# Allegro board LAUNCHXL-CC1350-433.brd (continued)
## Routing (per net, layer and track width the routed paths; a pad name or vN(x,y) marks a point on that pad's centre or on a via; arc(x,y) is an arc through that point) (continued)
VDDC: length 16.2
  TOP w0.203: U5.87 8.92,96.22 8.89,96.19 7.29,94.62 U5.115 2.49,94.62 C43.1 C44.1 C45.1
VDDR: length 25.7
  TOP w0.203: v1(27.03,36.55) 27.31,36.83 C16.1
  TOP w0.254: v3(27.58,34.01) 27.58,34.04 27.61,34.06 C9.1 28.42,35.46 28.42,35.61 28.55,35.74 U1.48 ; C16.1 27.38,37.24 U1.45
  TOP w0.508: v3(31.72,46.91) 31.6,46.79 31.12,46.79 ; C8.1 31.12,47.42 31.12,46.79 ; L1.2 31.12,46.79
  L3 w0.508: v3(31.72,46.91) 31.12,46.91 30.99,46.79 28.32,46.79 27.81,46.28 26.87,46.28 26.37,45.77 26.37,36.5 ; v1(27.03,36.55) 26.42,36.55 26.37,36.5 ; 26.37,36.5 26.37,35.89 27.58,34.67 v3(27.58,34.01)
VDDS: length 46.3
  TOP w0.203: v1(23.7,31.19) R67.1
  TOP w0.254: v3(37.47,41) 37.01,40.54 C4.1 36.83,40.23 U1.22 ; C7.1 29.87,43.61 30.58,42.9 U1.34 ; U1.44 27.94,37.72 v1(27.89,37.77) 27.36,37.77 C5.1 ; U1.13 36.78,35.74 C3.1 36.91,35.59 36.68,35.36 v3(36.68,35.05)
  TOP w0.406: 27.31,44.65 R1.2 27.38,43.71 C6.1 29.59,43.71 C7.1
  TOP w0.508: FL1.1 27.69,44.27 v3(27.84,44.27)
  L3 w0.203: v1(23.7,31.19) 26.06,31.19 28.32,33.45 28.32,37.34
  L3 w0.305: 28.32,37.34 v1(27.89,37.77)
  L3 w0.508: 27.89,42.85 27.89,43.61 27.84,43.66 v3(27.84,44.27) ; 27.89,42.85 27.94,42.9 35.56,42.9 36.68,41.78 36.68,40.97 ; 27.89,42.85 v1(27.89,37.77) ; v3(37.47,41) 36.7,41 36.68,40.97 ; 36.68,40.97 v3(36.68,35.05)
CC1350_RESET: length 77
  TOP w0.152: CR8.2 38.71,74.07 38.56,73.91 v1(38.56,73.71) ; R52.1 R51.2 ; v1(38.61,72.16) 38.91,71.86 45.95,71.86 46.41,72.31 46.41,75.34 45.67,76.05 P5.10
  TOP w0.203: R1.1 27.81,42.72 27.97,42.88 29.85,42.88 30.1,42.62 U1.35 ; C20.1 v1(24.82,42.72) ; 43.13,70 43.13,71.68 42.95,71.86 ; v1(38.61,72.16) 38.15,72.16 36.73,73.58 v1(25.48,73.58) v1(25.48,69.29)
  TOP w0.305: R1.1 C20.1
  L3 w0.152: v1(38.56,73.71) 38.56,73.23 38.61,73.18 v1(38.61,72.16)
  L3 w0.203: v1(25.48,73.58) 25.48,74.4 24.16,75.72 P4.12 ; v1(25.48,69.29) 25.48,52.96 24.82,52.3 v1(24.82,42.72)
CC1350_RXD: length 93.5
  TOP w0.203: v1(42.42,33.45) 41.38,32.41 34.11,32.41 32.59,33.93 U1.7 ; v1(42.42,59.21) 42.09,59.54 v1(19.08,59.54) 7.67,59.54 J1.7 ; v1(19.08,69.37) v1(19.08,73.46)
  L3 w0.203: v1(42.42,33.45) v1(42.42,59.21) ; v1(19.08,69.37) v1(19.08,59.54) ; P4.16 v1(19.08,73.46)
CC1350_SW_PWR: length 46.3
  TOP w0.203: v1(16.42,50.69) 16.41,50.67 J1.16 ; v1(24.59,32.11) R69.2 ; U1.43 27.81,38.23 27.38,38.66 v1(16.94,38.66)
  L3 w0.203: v1(16.42,50.69) 16.94,50.16 v1(16.94,38.66) 16.94,33.1 17.93,32.11 v1(24.59,32.11)
CC1350_SWO: length 52.7
  TOP w0.203: v1(34.77,44.91) 34.77,43.87 33.58,42.67 U1.28 ; v1(35.28,69.62) v1(35.28,72.16) ; J2.9 v1(35.15,58.29)
  L3 w0.203: v1(35.28,69.62) 35.28,65.13 35.64,64.77 35.64,58.78 v1(35.15,58.29) 34.77,57.91 v1(34.77,44.91) ; v1(35.28,72.16) 35.28,76.56 36.35,77.62 36.35,77.65 36.86,78.16 P4.2
CC1350_TCK: length 67.4
  TOP w0.152: 38.71,76.68 38.96,76.94 39.45,76.94 39.57,76.81 41.33,76.81 41.86,77.34 P5.4 ; 38.71,76.68 CR8.6 ; 38.71,76.68 v1(38.71,77.5)
  TOP w0.203: v1(37.26,77.04) 29.39,77.04 29.24,77.19 29.24,78.61 ; U1.25 35.08,42.37 v1(36.7,43.99) ; v1(36.7,50.7) R47.2 ; v1(37.57,68.58) 29.54,68.58 29.24,68.88 v1(29.24,72.95)
  L3 w0.203: v1(37.57,68.58) 37.57,56.46 37.08,55.98 37.08,52.2 36.7,51.82 v1(36.7,50.7) v1(36.7,43.99) ; v1(37.26,77.04) 38.25,77.04 v1(38.71,77.5) ; v1(29.24,72.95) 29.24,78.61
CC1350_TMS: length 67.9
  TOP w0.152: P5.2 38.51,78.1 38.2,77.8 CR8.7
  TOP w0.203: CR8.7 36.63,76.3 35.31,74.98 v1(28.58,74.98) v1(26.7,74.98) ; v1(28.58,72.67) 28.58,68.63 29.51,67.69 v1(38.28,67.69) ; U1.24 35.81,42.44 36.53,43.15 36.98,43.15 v1(37.64,43.81) ; R46.2 v1(37.64,53.21)
  L3 w0.203: v1(37.64,43.81) v1(37.64,53.21) 37.64,54.97 38.28,55.6 v1(38.28,67.69) ; P4.10 v1(26.7,74.98) ; v1(28.58,72.67) v1(28.58,74.98)
CC1350_TXD: length 90.9
  TOP w0.203: U1.8 33.1,33.93 34.14,32.89 40.92,32.89 v1(41.76,33.73) ; v1(40.16,62.08) v1(20.35,62.08) 7.67,62.08 J1.5 ; v1(21.62,69.49) v1(21.62,73.56)
  L3 w0.203: v1(21.62,69.49) 21.62,67.08 20.35,65.81 v1(20.35,62.08) ; v1(41.76,33.73) 41.76,43.69 40.77,44.68 40.77,61.47 v1(40.16,62.08) ; v1(21.62,73.56) 21.62,78.61
CC1350_VDD: length 157.6
  TOP w0.254: R59.2 47.57,31.88 47.12,32.33 R11.2 v3(46.3,32.46)
  TOP w0.305: v1(27.1,47.75) R2.2 R3.2 ; U4.8 C30.1 ; CR8.8 37.69,75.56 37.21,75.06 v1(37.21,74.8) 37.21,74.29 38.56,72.95 39.5,72.95 40.06,73.51 P5.1
  TOP w0.508: v3(11.73,71.3) 7.34,71.3 6.38,70.33 J1.1 ; R60.2 47.12,36.09 C30.1 47.09,35.41 v3(46.3,35.41) ; FL1.2 v1(27.1,47.75)
  L3 w0.254: v3(46.3,35.41) v3(46.3,32.46)
  L3 w0.305: 39.5,71.3 39.7,71.5 39.7,74.22 39.12,74.8 v1(37.21,74.8)
  L3 w0.508: P4.18 16.54,71.3 ; 16.54,71.3 v3(11.73,71.3) ; 16.54,71.3 27.1,71.3 ; v1(27.1,47.75) 27.1,71.3 ; 27.1,71.3 49.91,71.3 ; 49.91,71.3 54,71.3 55.7,69.6 55.7,45.87 54.84,45.01 54.84,36.14 54.31,35.61 52.27,35.61 P1.1 46.99,35.43 46.96,35.41 v3(46.3,35.41) ; 49.91,71.3 P10.3
DCDC_SW: length 2.4
  TOP w0.305: U1.33 31.09,44.37 L1.1
DIO1_RF_SW: length 85.8
  TOP w0.203: v1(43.05,33.1) 41.91,31.95 v1(34.29,31.95) 34.26,31.98 34.01,31.98 32.08,33.91 U1.6 ; J1.20 v1(10.67,45.59) ; v1(11.94,56.31) 24.13,56.31 25.98,54.46 v1(43.05,54.46) ; v1(31.06,29.44) U11.6
  L3 w0.203: v1(43.05,33.1) v1(43.05,54.46) ; v1(10.67,45.59) 11.15,46.08 11.15,55.52 v1(11.94,56.31) ; v1(31.06,29.44) 31.39,29.11 33.43,29.11 33.96,29.64 33.96,31.62 v1(34.29,31.95)
DIO4_SCL: length 78
  TOP w0.203: J1.17 7.72,46.79 v1(11.96,46.79) 22.05,46.79 23.01,47.75 R2.1 ; v1(41.12,33.99) 40.49,33.35 34.29,33.35 33.58,34.06 U1.9 ; v1(12.5,51.33) v1(40.08,51.33)
  L3 w0.203: v1(41.12,33.99) 41.12,43.1 40.08,44.15 v1(40.08,51.33) ; v1(12.5,51.33) 11.96,50.8 v1(11.96,46.79)
DIO5_SDA: length 71.8
  TOP w0.203: U1.10 34.09,34.16 34.49,33.76 40.03,33.76 v1(40.44,34.16) ; R3.1 24.18,46.71 23.67,46.71 20.9,43.94 v1(18.01,43.94) 8.03,43.94 J1.19 ; v1(39.47,49.63) 36.42,49.63 35.36,50.7 v1(18.01,50.7)
  L3 w0.203: v1(39.47,49.63) 39.47,43.76 40.44,42.8 v1(40.44,34.16) ; v1(18.01,50.7) v1(18.01,43.94)
DIO6_RLED: length 82.6
  TOP w0.203: J2.3 v1(40.26,65.91) ; U1.11 34.59,34.32 34.77,34.14 39.47,34.14 v1(39.8,34.47) ; v1(38.94,48.92) 36.22,48.92 35.03,50.11 v1(13.61,50.11)
  L3 w0.203: v1(39.8,34.47) 39.8,42.52 38.94,43.38 v1(38.94,48.92) 38.94,53.95 39.45,54.46 39.45,65.1 v1(40.26,65.91) ; v1(13.61,50.11) 12.67,49.17 12.67,41.63 P6.2
DIO7_GLED: length 97.8
  TOP w0.203: v1(39.24,34.77) 39.01,34.54 35.2,34.54 35.08,34.67 U1.12 ; J2.1 47.45,68.45 45.82,66.83 v1(38.94,66.83) v1(15.11,66.83)
  L3 w0.203: v1(38.94,66.83) 38.94,55.27 38.3,54.64 38.3,42.8 39.24,41.86 v1(39.24,34.77) ; P6.4 v1(15.11,66.83)
DIO8_MISO: length 45.1
  TOP w0.203: v1(46.81,51.92) 50.83,51.92 J2.14 ; U4.2 v1(48.67,32.46) ; U1.14 v1(44.48,36.22) ; v1(50.29,36.32) 50.32,36.35 ; 50.32,36.35 50.32,37.31 49.91,37.72 v1(47.98,37.72) ; 50.32,36.35 v1(50.32,34.37)
  L3 w0.203: v1(48.67,32.46) 50.11,32.46 50.32,32.66 v1(50.32,34.37) ; v1(47.98,37.72) 47.98,40.46 46.33,42.11 46.33,51.44 v1(46.81,51.92) ; v1(44.48,36.22) 46.1,36.22 46.33,35.99 49.96,35.99 v1(50.29,36.32)
DIO9_MOSI: length 40.3
  TOP w0.203: v1(46.48,54.46) 50.83,54.46 J2.12 ; 35.81,36.73 46.61,36.73 v1(46.99,37.11) 47.02,37.13 49.56,37.13 49.66,37.03 U4.5
  L3 w0.203: v1(46.99,37.11) 47.04,37.11 47.47,37.54 47.47,40.34 45.92,41.88 45.92,53.9 v1(46.48,54.46)
DIO10_SCLK: length 69
  TOP w0.203: J1.13 7.62,51.97 44.35,51.97 v1(44.68,51.64) ; U1.16 v1(46.25,37.24) ; v1(49.15,36.5) U4.6
  L3 w0.203: v1(44.68,51.64) 44.68,41.43 46.25,39.85 v1(46.25,37.24) 46.25,36.78 46.53,36.5 v1(49.15,36.5)
DIO11_CS: length 43.6
  TOP w0.203: v1(45.29,62.13) 50.88,62.13 J2.6 ; U1.17 v1(46.96,37.72)
  L3 w0.203: v1(46.96,37.72) 46.96,39.9 45.29,41.58 v1(45.29,62.13)
DIO12: length 46.2
  TOP w0.203: v1(46.58,64.36) 46.91,64.69 50.9,64.69 J2.4 ; U1.18 v1(48.44,38.23)
  L3 w0.203: v1(48.44,38.23) 48.44,40.64 46.71,42.37 46.71,50.67 47.27,51.23 47.27,57.58 46.58,58.27 v1(46.58,64.36)
DIO13_BTN1: length 97.5
  TOP w0.203: v1(47.29,65.28) 40.82,65.28 40.08,64.54 28.17,64.54 27.25,65.46 v1(17.73,65.46) ; J2.16 50.88,49.43 47.5,49.43 v1(47.17,49.1) ; v1(17.73,69.04) 17.73,73.51 17.04,74.19 7.52,74.19 R56.2 ; v1(49.02,38.73) U1.19
  L3 w0.203: v1(49.02,38.73) 48.79,38.96 48.79,40.84 47.17,42.47 v1(47.17,49.1) 47.17,50.19 47.78,50.8 47.78,64.8 v1(47.29,65.28) ; v1(17.73,65.46) v1(17.73,69.04)
DIO14_BTN2: length 56.3
  TOP w0.203: R55.2 48.51,70.89 v1(47.98,70.36) ; U1.20 v1(49.35,39.22) ; v1(47.83,46.86) 50.85,46.86 J2.18
  L3 w0.203: v1(49.35,39.22) 49.35,41.2 47.83,42.72 v1(47.83,46.86) 48.16,47.19 48.16,69.72 47.98,69.9 v1(47.98,70.36)
DIO15: length 21.7
  TOP w0.203: U1.21 v1(49.91,39.73)
  L3 w0.203: v1(49.91,39.73) 49.91,43.97 50.44,44.5 51.77,44.5 51.97,44.7 51.97,45.44 J2.20
DIO16_TDO: length 61.6
  TOP w0.152: P5.6 43.13,77.34 42.09,76.3 v1(39.8,76.3) CR8.5
  TOP w0.203: U1.26 34.59,42.62 35.99,44.02 v1(35.99,44.17) ; v1(35.99,48.08) 36.14,48.08 36.17,48.11 R48.2 ; v1(35.92,76.3) v1(31.8,76.3) ; v1(36.93,69.82) 36.93,72.36 36.5,72.8 v1(31.8,72.8)
  L3 w0.203: v1(35.99,44.17) v1(35.99,48.08) 35.99,56.24 36.96,57.2 36.96,67.67 36.5,68.12 36.5,69.39 v1(36.93,69.82) ; 31.78,78.61 31.78,76.33 v1(31.8,76.3) v1(31.8,72.8) ; v1(35.92,76.3) v1(39.8,76.3)
DIO17_TDI: length 57.6
  TOP w0.152: P5.8 44.4,77.34 42.95,75.9 41.28,75.9 v1(39.19,73.81) CR8.3
  TOP w0.203: v1(35.99,70.21) v1(35.99,72.26) ; v1(36.63,74.32) v1(34.32,74.32) ; U1.27 34.09,42.62 35.33,43.87 35.33,45.49 v1(35.43,45.59) R49.2
  L3 w0.152: 38.68,74.32 v1(39.19,73.81)
  L3 w0.203: v1(35.99,72.26) 35.99,73.69 v1(36.63,74.32) 38.68,74.32 ; v1(35.99,70.21) 35.99,65.3 36.3,65 36.3,57.91 35.43,57.05 v1(35.43,45.59) ; v1(34.32,74.32) P4.4
DIO19_CTS: length 34.4
  TOP w0.203: J2.7 35.36,60.83 35.33,60.86 v1(34.87,60.86) ; U1.29 33.1,42.77 34.32,43.99 v1(34.32,45.52)
  L3 w0.203: v1(34.32,45.52) 34.32,60.3 v1(34.87,60.86)
DIO20_FLASH_CS: length 65.9
  TOP w0.203: v1(43.76,33.38) R11.1 ; U1.30 32.59,42.93 33.68,44.02 v1(33.68,46.33) 40.16,46.33 40.72,46.89 v1(43.76,46.89) ; J2.5 v1(34.06,63.37)
  TOP w0.254: U4.1 47.96,33.05 47.62,33.38 R11.1
  L3 w0.203: v1(43.76,46.89) v1(43.76,33.38) ; v1(34.06,63.37) 33.68,62.99 v1(33.68,46.33)
DIO21: length 35
  TOP w0.203: J1.15 7.62,49.43 v1(32.99,49.43) ; U1.31 32.08,43.03 32.99,43.94 v1(32.99,45.24)
  L3 w0.203: v1(32.99,49.43) v1(32.99,45.24)
DIO22: length 41.5
  TOP w0.203: v1(31.75,57.02) 7.65,57.02 J1.9 ; v1(32.33,44.53) 32.33,43.97 31.6,43.23 U1.32
  L3 w0.203: v1(32.33,44.53) 32.33,56.44 v1(31.75,57.02)
DIO23_ANALOG: length 47.6
  TOP w0.203: v1(24.05,64.49) 23.75,64.8 9.88,64.8 9.75,64.67 7.62,64.67 J1.3 ; U1.36 29.59,42.37 29.44,42.52 28.37,42.52 27.76,41.91 24.36,41.91 v1(24.16,42.11)
  L3 w0.203: v1(24.16,42.11) 24.16,53.11 24.87,53.82 24.87,63.68 v1(24.05,64.49)
DIO24_ANALOG: length 35.7
  TOP w0.203: U1.37 28.32,41.22 28.12,41.43 23.72,41.43 v1(23.42,41.73) ; J1.11 7.67,54.46 22.99,54.46 v1(23.42,54.03)
  L3 w0.203: v1(23.42,41.73) v1(23.42,54.03)
DIO25_ANALOG: length 42.1
  TOP w0.203: v1(22.02,63.58) 10.62,63.58 10.41,63.37 J1.6 ; U1.38 28.22,40.72 27.91,41.02 23.06,41.02 v1(22.61,41.48)
  L3 w0.203: v1(22.02,63.58) 22.33,63.27 22.35,63.27 22.61,63.02 v1(22.61,41.48)
DIO26_ANALOG: length 39.5
  TOP w0.203: v1(20.9,60.76) 8.99,60.76 J1.8 ; U1.39 28.09,40.23 27.74,40.59 22.25,40.59 v1(21.67,41.17)
  L3 w0.203: v1(21.67,41.17) 21.67,59.99 v1(20.9,60.76)
DIO27_ANALOG: length 37.6
  TOP w0.203: U1.40 28.02,39.73 27.66,40.08 21.06,40.08 v1(20.6,40.54) ; v1(20.17,57.94) 19.81,58.29 J1.10
  L3 w0.203: v1(20.6,40.54) 20.6,57.51 v1(20.17,57.94)
DIO28_ANALOG: length 35.4
  TOP w0.203: v1(18.97,55.45) 10.29,55.45 9.98,55.75 J1.12 ; v1(19.69,39.95) 20.07,39.57 27.56,39.57 27.91,39.22 U1.41
  L3 w0.203: v1(19.69,39.95) 19.69,40 19.58,40.11 19.58,54.84 v1(18.97,55.45)
DIO29_ANALOG: length 34.3
  TOP w0.203: U1.42 27.84,38.73 27.46,39.12 18.8,39.12 v1(18.39,39.52) ; v1(18.19,53.24) 10.01,53.24 9.98,53.21 J1.14
  L3 w0.203: v1(18.39,39.52) 18.87,40 18.87,52.55 v1(18.19,53.24)
IRSTN: length 17.3
  TOP w0.152: v1(6.83,109.5) 7.34,110.01 9.96,110.01 11.07,108.89 11.07,105.64 11.81,104.9 R20.2 ; v1(3.51,106.1) 5.31,107.9 v1(5.31,109.5)
  L3 w0.152: v1(5.31,109.5) v1(6.83,109.5)
ITCK: length 12.4
  TOP w0.152: v1(2.11,110.01) 0.81,108.71 0.81,101.5 1.7,100.61 U5.100
ITDI: length 10.3
  TOP w0.152: U5.98 1.8,101.4 1.45,101.75 1.45,105.18 2.79,106.53 2.79,108.13 v1(3.38,108.71)
ITDO: length 13.2
  TOP w0.152: U5.97 2.08,101.8 1.8,102.08 1.8,105.11 4.8,108.1 4.8,109.91 v1(3.4,111.3)
ITMS: length 9.2
  TOP w0.152: U5.99 2.84,101.02 2.82,100.99 1.75,100.99 1.14,101.6 1.14,106.55 v1(2.11,107.49)
LP_RESET: length 17.4
  TOP w0.203: J2.10 50.9,59.51 v1(46,59.51) ; v1(45.67,68.4) R51.1
  L3 w0.203: v1(45.67,68.4) 46,68.07 v1(46,59.51)
Net_7: length 1.7
  TOP w0.152: 19.2,92.61 20.29,92.61 v1(20.7,93.01)
Net_24:
  vias: v2(21.59,7.19) v2(23.6,2.18)
Net_25:
  vias: v2(19.61,7.19) v2(21.59,2.18)
Net_26:
  vias: v2(17.6,7.19) v2(19.61,2.18)
Net_27:
  vias: v2(15.6,7.19) v2(17.6,2.18)
Net_28:
  vias: v2(13.59,7.19) v2(15.6,2.18)
Net_29:
  vias: v2(11.61,7.19) v2(13.59,2.18)
Net_30:
  vias: v2(9.6,7.19) v2(11.61,2.18)
Net_31:
  vias: v2(7.59,7.19) v2(9.6,2.18)
Net_32:
  vias: v2(5.61,7.19) v2(5.61,2.18) v2(7.59,2.18)
Net_33:
  vias: v2(23.6,7.19) v2(25.6,2.18)
USB_DM: length 14.1
  TOP w0.152: J6.2 10.74,114 v1(10.74,112.88) 10.8,112.83 10.8,112.19 CR6.5 ; v1(8.69,110.9) 7.29,110.9 6.4,110.01 6.4,104.11 6.5,104.01 U5.93
  L3 w0.152: v1(10.74,112.88) 9.07,111.2 v1(8.69,110.9)
USB_DP: length 15.7
  TOP w0.152: CR6.4 11.3,112.8 v1(11.38,112.88) 11.4,112.9 J6.3 ; U5.94 6.1,110.44 7.04,111.38 8.92,111.38 v1(9.42,110.87)
  L3 w0.152: v1(11.38,112.88) v1(9.42,110.87)
USB_ID: length 14.6
  TOP w0.152: CR6.2 10.8,111.61 v1(10.8,111) 10.11,111 9.4,111.71 6.78,111.71 5.79,110.72 5.79,106.88 5.59,106.68 R19.2 ; J6.4 12.04,114 v1(12.04,112.85)
  L3 w0.152: v1(10.8,111) 10.8,111.66 11.68,112.55 11.73,112.55 v1(12.04,112.85)
USB_VBUS: length 56.2
  TOP w0.152: U7.8 v1(14.71,110.59) ; R22.2 v1(3.56,86.51)
  TOP w0.203: R66.1 3.38,103.78 3.07,103.78 v1(2.59,103.3)
  TOP w0.305: U7.2 U7.1 11.71,110.59 12.19,111.07 C48.1 ; J6.1 10.11,112.9 v1(10.08,112.88) 10.08,112.42 CR6.6
  TOP w0.508: v1(12.19,111.91) C48.1
  L3 w0.508: P4.19 11.86,83.31 7.37,83.31 4.17,86.51 v1(3.56,86.51) 0.76,89.31 0.76,103.4 ; 11.23,110.11 4.7,110.11 3.94,109.35 1.85,109.35 0.76,108.25 0.76,103.4 ; v1(2.59,103.3) 0.84,103.3 0.76,103.4
V-SENSE: length 41.6
  TOP w0.152: v1(25.7,85.12) C55.1 U10.2 ; v1(21.69,85.12) C53.1 U8.2 ; v1(29.69,85.12) C57.1 U9.2
  TOP w0.305: 38.66,85.8 38.66,86.74 39.8,87.91 44.91,87.91 45.69,87.1 P7.1 47.19,86.51 47.9,85.8 47.9,83.16 P10.2 ; 38.66,85.8 38.35,85.5 36.2,85.5 34.75,84.05 30.76,84.05 v1(29.69,85.12) ; 38.66,85.8 CR7.8
  L3 w0.305: v1(21.69,85.12) 22.05,84.76 22.83,84.76 22.89,84.71 24.82,84.71 25.22,85.12 v1(25.7,85.12) 26.19,85.12 26.57,84.71 28.83,84.71 29.21,85.12 v1(29.69,85.12)
XDS_RESET: length 11.6
  TOP w0.152: U10.1 23.77,84.71 23.57,84.91 23.57,85.93 23.52,86 U10.6 v1(23.52,87.71) ; v1(22.81,89.71) 21.79,90.7 21.79,91.8 R58.1 20.85,92.3 20.75,92.2 U5.40
  L3 w0.152: v1(22.81,89.71) 23.5,89.71 23.8,89.41 23.8,87.99 v1(23.52,87.71)
XDS_RESET_LS: length 64.6
  TOP w0.152: R57.2 v1(16.99,114.3) ; P7.10 38.79,81.92 36.83,83.87 v1(36.83,83.95) 37.29,84.4 CR7.2 ; v1(23.5,83.41) 23.5,84.07 U10.15 23.52,82.98 24.16,82.35 P4.11
  L3 w0.152: 29.87,84.53 30.3,84.96 30.3,86.11 26.9,89.51 25.3,89.51 25.27,89.48 24.43,89.48 23.75,90.17 23.75,113.33 22.78,114.3 v1(16.99,114.3) ; 29.87,84.53 29.51,84.53 29.29,84.3 24.41,84.3 v1(23.5,83.41) ; 29.87,84.53 30.53,84.53 30.76,84.3 36.47,84.3 v1(36.83,83.95)
XDS_RX: length 3.1
  TOP w0.152: U8.8 18.69,86.89 19.13,87.33 19.13,89.33 U5.33
XDS_RX_LS: length 10.5
  TOP w0.152: R61.2 21.72,81.25 20.32,79.86 18.01,79.86 17.75,80.11 17.75,82.47 18.69,83.41 U8.13
XDS_SWO: length 7.2
  TOP w0.152: U5.25 14.91,88.75 15.06,88.9 17.96,88.9 18.11,88.75 18.11,86.31 U8.9
XDS_SWO_LS: length 23.8
  TOP w0.152: U8.12 v1(17.81,84.71) ; R62.2 v1(36.4,83.26) 36.86,82.8 P4.1
  L3 w0.152: v1(17.81,84.71) 19.81,82.7 26.9,82.7 27.43,83.24 30.28,83.24 30.89,83.85 35.81,83.85 v1(36.4,83.26)
XDS_TCK: length 10.4
  TOP w0.152: v1(23.29,89.2) 23.6,88.9 25.7,88.9 27.51,87.1 U9.6 ; U5.35 19.2,90.2 20.14,90.2 20.7,89.66 v1(20.7,89.2)
  L3 w0.152: v1(23.29,89.2) v1(20.7,89.2)
XDS_TDI: length 10.2
  TOP w0.152: U9.7 27.1,87.05 25.58,88.57 23.22,88.57 20.52,91.26 20.5,91.26 20.35,91.41 U5.38
XDS_TDI_LS: length 26.6
  TOP w0.152: CR7.3 37.9,83.54 38.63,82.8 40.01,82.8 40.41,83.21 41.35,83.21 41.88,82.65 P7.8 41.88,81.15 40.69,79.96 34.9,79.96 ; 34.9,79.96 28.45,79.96 27.94,80.47 27.94,81.86 27.1,82.7 U9.14 ; 34.9,79.96 34.34,80.52 34.34,81.13 P4.3
XDS_TDO: length 10.1
  TOP w0.152: U9.9 26.29,86.11 26.29,87.3 25.4,88.19 23.11,88.19 20.29,91.01 U5.37
XDS_TDO_LS: length 31.6
  TOP w0.152: 43.23,80.31 R63.2 43.23,80.31 ; 43.23,80.31 43.23,79.96 42.82,79.55 v1(41.15,79.55) ; 43.23,80.31 43.15,80.37 P7.6 43.15,82.65 41.91,83.9 39.4,83.9 CR7.5 ; v1(25.45,82.22) 25.45,82.75 25.81,83.11 25.81,84.25 26.26,84.71 U9.12
  L3 w0.152: 31.89,79.93 25.76,79.93 25.45,80.24 v1(25.45,82.22) ; 31.89,79.93 40.34,79.93 ; 31.89,79.93 31.89,81.04 31.78,81.15 ; 40.36,79.93 40.74,79.55 v1(41.15,79.55)
XDS_TMS: length 6.1
  TOP w0.152: U10.8 22.71,88.09 20.19,90.6 U5.36
XDS_TMS_DIR: length 12.9
  TOP w0.152: v1(18.59,87.5) 18.59,88.8 18.19,89.2 14.86,89.2 14.5,88.85 U5.24 ; U10.5 23.9,87.12 v1(24,87.2)
  L3 w0.152: v1(18.59,87.5) 18.9,87.2 v1(24,87.2)
XDS_TMS_LS: length 34.6
  TOP w0.152: U10.13 22.71,82.8 22.89,82.63 22.89,80.42 23.44,79.86 25.4,79.86 P4.9 ; R65.2 46.3,82.02 46.18,81.92 P7.2 45.69,83.9 44.7,84.91 v1(41,84.91) CR7.7
  L3 w0.152: v1(41,84.91) 41,84 39.27,82.27 27.81,82.27 P4.9
XDS_TX: length 4.5
  TOP w0.152: U8.6 19.51,88.52 20.19,89.2 20.19,89.66 20.04,89.81 U5.34
XDS_TX_LS: length 3.4
  TOP w0.152: P4.15 19.81,81.89 19.81,83.26 19.51,83.54 U8.15
XDS_VCC: length 86.7
  TOP w0.152: v1(29.69,85.9) C56.1 U9.4 U9.3 ; C38.1 17.12,105.82 R17.2 17.12,106.63 v1(17.09,106.65) ; R33.2 C47.1 v1(16.61,109.5) ; v1(8.89,85.09) R18.2 8.89,85.7 8.79,85.6 C42.1 ; v1(20.7,91.69) 21.03,91.39 R58.2 ; U8.3 U8.4 C52.1 v1(21.69,85.9) ; v1(25.7,85.9) C54.1 U10.4 U10.3
  TOP w0.203: 15.49,86.51 C35.1 v1(15.49,85.85) ; 15.49,86.51 15.29,86.72 15.29,87.91 U5.26 ; 15.49,86.51 16.1,87.1 U5.28 ; U5.39 19.2,91.8 20.6,91.8 v1(20.7,91.69) ; v1(21.89,103) R39.1 R27.1 ; U5.113 2.39,95.4 C36.1 v1(1.65,95.5) ; U5.52 U5.51 19.2,96.6 C39.1 C40.1 v1(22.3,96.6) ; U5.101 2.59,100.2 C37.1 v1(1.75,100) ; v1(22.61,99.69) R30.2 ; v1(7.59,104.39) 7.7,104.29 U5.90 ; U5.122 3.81,91.8 v1(2.74,91.8) ; U5.69 16.1,104.34 16.21,104.44 C38.1 ; U5.47 v1(20.27,95) ; v1(11.43,86.72) 11.3,86.84 U5.16 ; v1(12.09,104.37) 12.09,103.33 U5.79 ; U5.7 U5.8 8.1,86.69 C41.1 C42.1 ; R31.2 v1(20.6,104.9)
  TOP w0.305: P10.1 49.91,87 48.31,88.6 37.59,88.6 35.89,86.89 30.71,86.89 v1(29.69,85.9) ; U7.3 U7.4 C49.1 v1(11.71,106.3)
  L3 w0.152: v1(16.61,109.5) 16.61,107.11
  L3 w0.305: 17.6,87.5 18.59,86.51 21.11,86.51 v1(21.69,85.9) 22.1,86.31 25.3,86.31 v1(25.7,85.9) 26.04,86.23 29.36,86.23 v1(29.69,85.9) ; P4.17 16.54,84.81 v1(15.49,85.85)
  L3 w0.508: 15.19,85.19 15.24,85.19
  vias: v1(2.01,106.4)
N1013277: length 7.1
  TOP w0.254: Y2.3 22.96,36.25 23.93,35.28 23.93,35.23 25.12,35.23 25.81,35.92 27.33,35.92 28.14,36.73 28.85,36.73
N1013855: length 4.2
  TOP w0.203: 27.95,28.05 27.97,28.04 28.91,28.98 U11.10
  TOP w0.305: 27.95,28.05 27.97,28.04 27.94,28.04 C11.1 L12.1
N1013859: length 3.9
  TOP w0.203: L30.1 29.39,28.19 U11.1
  TOP w0.305: C22.1 27.74,26.39 L27.1 27.84,26.64 L30.1
N1013907: length 3.2
  TOP w0.356: 26.33,24.98 26.34,24.99 25.65,24.99 25.58,25.1 ; 25.58,25.1 25.58,25.68 25.57,25.67 ; 25.58,25.1 C12.1 L13.1
N1013927: length 2.1
  TOP w0.305: 23.71,23.23 C13.1 L14.1
N1013977: length 3.6
  TOP w0.356: A1.1 L33.1 C71.2
N1014101: length 10.5
  TOP w0.203: Y1.1 35.41,28.83 34.7,28.83 34.19,29.34 34.19,30.76 31.75,33.2 31.52,33.2 31.09,33.63 U1.4
  TOP w0.305: C17.1 37.16,28.42 36.3,28.42 36.07,28.65 Y1.1
N1014113: length 8
  TOP w0.203: Y1.2 34.32,31.14 31.6,33.86 U1.5
  TOP w0.305: Y1.2 36.17,31.14 36.4,31.37 C18.1
N1018952: length 5
  TOP w0.254: U1.47 28.42,36.22 27.53,35.33 26.19,35.33 25.5,34.65 25.22,34.65 Y2.1
N1105722: length 1.4
  TOP w0.305: R15.1 CR1.2
N1105771: length 1.3
  TOP w0.305: CR2.2 12.55,34.62 R14.1
N1105824: length 2.2
  TOP w0.305: P6.1 12.57,36.86 R14.2
N1106228: length 2.1
  TOP w0.305: P6.3 R15.2
N1176544: length 6.4
  TOP w0.254: R46.1 J2.13
N1176548: length 6.4
  TOP w0.254: R47.1 48.44,50.7 48.46,50.67 J2.15
N1176568: length 6.4
  TOP w0.203: J2.17 43.23,48.13 R48.1
N1177007: length 6.4
  TOP w0.254: R49.1 J2.19
N1240270: length 23
  TOP w0.152: U9.15 27.51,83.31 27.58,83.24 28.14,83.24 v1(28.68,82.7) 28.73,82.7 28.88,82.55 28.91,82.55 29.24,82.22 29.24,81.15 ; P7.4 44.42,83.13 43.15,84.4 v1(40.21,84.4) CR7.6
  L3 w0.152: v1(28.68,82.7) 37.9,82.7 39.6,84.4 v1(40.21,84.4)
N1288065: length 1.8
  TOP w0.152: SW2.3 54.71,72.77 54.71,72.14 54.38,71.81 R55.1
N1288098: length 1.3
  TOP w0.152: R56.1 5.08,72.72 SW1.4
N1299607: length 22.1
  TOP w0.203: J2.11 v1(41.58,55.75) ; v1(41.2,68.5) 41.81,68.5 41.83,68.53 42.16,68.53 R52.2
  L3 w0.203: v1(41.2,68.5) 41.2,56.13 v1(41.58,55.75)
N1384129: length 4.7
  TOP w0.152: R57.1 19.71,115.6 SW3.3
N1393569: length 1.6
  TOP w0.254: C19.1 36.65,41.25 36.65,40.97 36.4,40.72 U1.23
N1403554: length 9.4
  TOP w0.203: U1.3 30.58,33.6 30.96,33.22 30.96,32.94 L29.2
  TOP w0.305: L29.2 v1(31.34,31.93) C58.1 ; C65.1 v1(28.22,31.9) L28.2
  L3 w0.203: v1(28.22,31.9) 28.22,32.38 28.4,32.56 31.17,32.56 31.34,32.38 v1(31.34,31.93)
N1414078: length 2.1
  TOP w0.356: C69.1 C14.1 20.83,20.35 21.55,21.07
N1417883: length 3.8
  TOP w0.254: L28.1 29.21,33.12 29.59,33.5 U1.1
  TOP w0.305: L28.1 29.34,32.41 C63.1
N1418253: length 3.7
  TOP w0.254: U1.2 30.1,33.48 30.35,33.22 L29.1
  TOP w0.305: C64.1 L29.1
N1419138: length 4.1
  TOP w0.152: U11.4 30.58,27.76 31.17,27.18 31.15,27.17
  TOP w0.305: 31.93,26.24 31.93,26.42 31.17,27.18 31.15,27.17 ; 31.93,26.24 31.94,26.25 31.93,26.24 ; 31.93,26.24 32.05,26.24 L21.1
N1419146: length 4.5
  TOP w0.152: U11.5 30.94,28.98 31.75,28.17 31.75,28.09 ; 31.75,28.09 31.75,27.86 L31.1 31.8,28.04 31.75,28.09
  TOP w0.305: C60.1 33.4,26.31 L11.1 31.9,27.81 L31.1
N1419182: length 3.7
  TOP w0.356: 34.25,25.67 34.24,25.68 34.19,25.63 34.19,24.69 ; 34.19,24.69 C61.1 35.31,23.57 L25.1 ; 34.19,24.69 34.01,24.87 33.43,24.87 33.44,24.85
N1419210: length 2.5
  TOP w0.305: L26.1 36.7,21.64 36.7,21.74 ; 36.7,21.74 36.69,21.73 36.7,21.74 ; 36.7,21.74 35.94,22.5 35.94,22.68 35.95,22.67
N1419230: length 2.8
  TOP w0.356: C24.1 40.44,17.91 40.77,17.58 C59.1 A2.1
N1419286: length 2.4
  TOP w0.356: 38.94,19.41 C68.2 38.94,19.41 ; 38.94,19.41 38.14,20.21 ; 38.94,19.41 39.78,18.57 39.78,18.54 39.76,18.55
N1420906: length 1.1
  TOP w0.203: U11.7 30.18,30.02 30.35,30.2 C64.2
N1421284: length 5.1
  TOP w0.203: v1(26.16,30.53) 26.16,30.99 25.93,31.22 R68.2 ; U11.9 v1(28.83,29.44)
  L3 w0.203: v1(28.83,29.44) 28.75,29.36 27.33,29.36 v1(26.16,30.53)
N1433060: length 3
  TOP w0.356: C71.1 L32.1 21.13,18.59 20.76,18.96
N1447877: length 1.2
  TOP w0.203: R59.1 49.07,32.13 49.15,32.21 U4.3
N1447884: length 1.2
  TOP w0.254: R60.1 48.67,36.32 U4.7
N1465309: length 1.2
  TOP w0.203: U11.8 29.79,29.92 29.34,30.38 C63.2
N1466589: length 7.5
  TOP w0.356: 19.47,20.26 18.16,21.56 18.16,24.61 17.48,25.02 P11.1
N1466981: length 8.1
  TOP w0.356: P12.1 40.46,24.76 40.31,24.61 40.31,19.3 40.44,19.18 40.45,19.19
N1587996: length 3.8
  TOP w0.152: R17.1 R21.1 R20.1 15.7,104.39 U5.70
N1588002: length 2.1
  TOP w0.152: U5.60 20.6,100.2 R30.1
N1588004: length 3.1
  TOP w0.152: 15.7,107.98 15.52,108.15 U7.5 ; 15.7,107.98 R34.2 15.7,107.98 ; 15.7,107.98 16.61,107.98 ; 16.61,107.98 C47.2 16.61,107.98 ; 16.61,107.98 17.04,107.98 17.07,108 R33.1
N1588016: length 2.2
  TOP w0.152: R28.2 20.98,98.83 19.99,99.8 19.2,99.8 U5.59
N1588028: length 2.3
  TOP w0.152: R24.1 R22.1 U5.1
N1588034: length 3.6
  TOP w0.152: Y3.3 7.42,106.32 7.49,106.25 C34.1 8.1,104.65 U5.89
N1588038: length 7.6
  TOP w0.152: U5.88 8.51,104.29 8.76,104.55 10.13,104.55 10.41,104.83 10.41,105.26 C33.1 10.29,105.38 10.44,105.54 10.44,105.56 10.64,105.77 10.64,107.98 10.31,108.31 Y3.1
N1588066: length 5.9
  TOP w0.152: U6.3 10.52,85.01 C50.1 C32.1 R18.1 8.51,86.89 U5.9
N1588110: length 2
  TOP w0.152: U5.95 5.69,103.3 5.69,104.47 5.59,104.57 R19.1
N1588130: length 2.2
  TOP w0.152: R39.2 20.96,102.41 20.57,102.01 20.57,101.98 19.99,101.4 U5.63
N1588132: length 1.9
  TOP w0.152: U5.61 R29.1
N1588134: length 2.1
  TOP w0.152: U5.62 19.2,100.99 20.6,100.99 20.98,101.37 R27.2
N1588248: length 3.9
  TOP w0.152: 18.34,104.9 R31.1 ; 18.34,104.9 C46.1 ; 18.34,104.9 17.73,104.29 16.64,104.29 16.51,104.17 U5.68
N1588328: length 7.1
  TOP w0.152: R23.2 1.5,86.79 2.82,86.79 4.93,88.9 5.89,88.9 6.1,88.7 U5.3
N1588330: length 6.2
  TOP w0.152: U5.4 6.5,88.85 6.15,89.2 4.8,89.2 2.87,87.27 2.21,87.27 R25.2
N1588336: length 3.6
  TOP w0.305: CR6.1 10.11,111.61 9.5,112.22 9.5,112.7 9.27,113 8.08,113 7.77,113.31 v1(7.7,113.31)
  vias: v1(7.29,114.6) v1(15.19,113.61) v1(15.6,114.5)
N1588554: length 1.5
  TOP w0.152: U5.96 C70.1 4.67,103.28 R66.2
N15894280: length 1
  TOP w0.152: R23.1 CR4.2
N15894940: length 1
  TOP w0.152: R25.1 CR5.2

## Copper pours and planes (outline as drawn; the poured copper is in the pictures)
GND on TOP (solid shape): 23.27,84.61 22.25,84.61 22.25,86 23.27,86
GND on TOP (solid shape): 4.6,114.6 0.56,114.6 0.56,118.15 0.78,118.52 1.15,118.75 4.6,118.75
GND on TOP (solid shape): 57.33,118.75 57.58,118.62 57.78,118.44 57.87,118.3 57.94,118.15 57.94,114.6 53.7,114.6 53.7,118.75
GND on BOTTOM (solid shape): 4.6,114.6 0.56,114.6 0.56,118.15 0.78,118.52 1.15,118.75 4.6,118.75
GND on BOTTOM (solid shape): 57.33,118.75 57.58,118.62 57.78,118.44 57.87,118.3 57.94,118.15 57.94,114.6 53.7,114.6 53.7,118.75
GND on L2 (solid shape): 4.6,114.6 0.56,114.6 0.56,118.15 0.78,118.52 1.15,118.75 4.6,118.75
GND on L2 (solid shape): 57.33,118.75 57.58,118.62 57.78,118.44 57.87,118.3 57.94,118.15 57.94,114.6 53.7,114.6 53.7,118.75
GND on L3 (solid shape): 4.6,114.58 0.56,114.58 0.56,118.13 0.78,118.49 1.15,118.72 4.6,118.72
GND on L3 (solid shape): 57.33,118.75 57.58,118.62 57.78,118.44 57.87,118.3 57.94,118.15 57.94,114.6 53.7,114.6 53.7,118.75
GND on TOP: 0.56,15.01 0.56,68.5 0.81,69.99 1.54,71.32 2.75,74.8 1.54,78.29 1.38,78.51 1.24,78.74 0.73,79.88 0.56,81.1 0.56,117.83 0.82,118.48 1.47,118.75 6.45,118.75 6.45,117.55 6.68,117.55 6.68,112.8 16.1,112.8 16.1,117.55 16.36,117.55 16.36,118.75 57.05,118.75 57.68,118.47 57.94,117.83 57.94,81.1 57.77,79.88 57.28,78.74 57.13,78.51 56.96,78.29 55.74,74.8 56.96,71.32 57.69,69.99 57.94,68.5 57.94,15.01 ; 20 cut-outs
GND on BOTTOM: 0.56,15.01 0.56,68.5 0.81,69.99 1.54,71.32 2.75,74.8 1.54,78.29 1.38,78.51 1.24,78.74 0.73,79.87 0.56,81.1 0.56,117.83 0.82,118.48 1.47,118.75 6.45,118.75 6.45,112.9 16.36,112.9 16.36,118.75 57.05,118.75 57.68,118.47 57.94,117.83 57.94,81.1 57.77,79.88 57.28,78.74 57.13,78.51 56.96,78.29 55.74,74.8 56.96,71.32 57.69,69.99 57.94,68.5 57.94,15.01 ; 3 cut-outs
GND on L2: 57.94,81.1 57.8,79.97 57.39,78.92 57.18,78.6 56.96,78.29 55.74,74.8 56.96,71.32 57.69,69.99 57.94,68.5 57.94,14.99 27.53,14.99 26.9,15.62 0.56,15.62 0.56,68.5 0.81,69.99 1.54,71.32 2.75,74.8 1.54,78.29 1.31,78.6 1.11,78.92 0.7,79.98 0.56,81.1 0.56,117.64 0.58,117.63 0.61,117.63 0.65,117.64 0.69,117.68 1.12,118.24 1.73,118.62 1.78,118.64 1.8,118.69 1.8,118.72 1.79,118.75 6.45,118.75 6.45,112.85 16.05,112.85 16.05,117.55 16.36,117.55 16.36,118.75 56.93,118.75 56.92,118.72 56.87,118.54 56.87,118.49 56.9,118.44 57.32,118.1 57.63,117.65 57.67,117.61 57.73,117.6 57.91,117.65 57.94,117.66
GND on L3: 0.51,15.01 0.51,68.5 0.76,69.99 1.49,71.32 2.7,74.8 1.49,78.29 1.33,78.51 1.19,78.74 0.68,79.87 0.51,81.1 0.51,117.83 0.77,118.48 1.42,118.75 6.4,118.75 6.4,117.55 8,117.55 8,115.44 10.01,115.44 10.01,117.55 12.7,117.55 12.7,115.44 14.71,115.44 14.71,117.55 16.31,117.55 16.31,118.75 57,118.75 57.63,118.47 57.89,117.83 57.89,81.1 57.72,79.88 57.23,78.74 57.08,78.51 56.91,78.29 55.69,74.8 56.91,71.32 57.64,69.99 57.89,68.5 57.89,15.01 ; 16 cut-outs
Net_12 on TOP (solid shape): 37.9,14.25 39.09,14.25 39.09,15.01 40.11,15.01 40.11,12.98 32.11,12.98 32.11,10.29 37.9,10.29 37.9,11.1 36.91,11.1 36.91,12.32 40.03,12.32 40.54,13.06 40.54,15.01 41,15.01 41,12.93 40.11,11.61 40.11,11.1 39.09,11.1 39.09,9.3 55.5,9.3 55.5,8.08 29.92,8.08 29.92,14.25 36.91,14.25 36.91,15.01 37.9,15.01
Net_24 on BOTTOM (solid shape): 21.26,6.83 21.25,7.53 21.95,7.54 22.94,6.55 23.05,6.39 23.09,6.2 23.09,3.4 23.95,2.54 23.95,1.83 23.24,1.83 22.23,2.84 22.13,3.01 22.1,3.2 22.1,5.99
Net_25 on BOTTOM (solid shape): 19.25,6.83 19.25,7.54 19.96,7.54 20.96,6.55 21.05,6.39 21.08,6.2 21.08,3.4 21.95,2.54 21.96,1.84 21.26,1.83 20.24,2.84 20.13,3.01 20.09,3.2 20.09,5.99
Net_26 on BOTTOM (solid shape): 17.25,6.83 17.25,7.54 17.96,7.54 18.95,6.55 19.05,6.39 19.08,6.2 19.08,3.4 19.96,2.54 19.96,1.83 19.25,1.83 18.24,2.84 18.13,3.01 18.08,3.2 18.08,5.99
Net_27 on BOTTOM (solid shape): 15.24,6.83 15.24,7.54 15.95,7.54 16.94,6.55 17.05,6.39 17.09,6.2 17.09,3.4 17.96,2.54 17.96,1.83 17.25,1.83 16.23,2.84 16.12,3.01 16.08,3.2 16.08,5.99
Net_28 on BOTTOM (solid shape): 13.26,6.83 13.26,7.54 13.97,7.54 14.94,6.55 15.05,6.39 15.09,6.2 15.09,3.4 15.95,2.54 15.95,1.83 15.24,1.83 14.22,2.84 14.13,3.01 14.1,3.2 14.1,5.99
Net_29 on BOTTOM (solid shape): 11.25,6.83 11.25,7.54 11.96,7.54 12.95,6.55 13.05,6.39 13.08,6.2 13.08,3.4 13.94,2.54 13.96,1.84 13.26,1.83 12.24,2.84 12.13,3.01 12.09,3.2 12.09,5.99
Net_30 on BOTTOM (solid shape): 9.25,6.83 9.25,7.54 9.96,7.54 10.95,6.55 11.06,6.39 11.1,6.2 11.1,3.4 11.96,2.54 11.96,1.83 11.25,1.83 10.24,2.84 10.12,3.01 10.08,3.2 10.08,5.99
Net_31 on BOTTOM (solid shape): 7.24,6.83 7.24,7.54 7.95,7.54 8.94,6.55 9.05,6.39 9.09,6.2 9.09,3.4 9.96,2.54 9.96,1.83 9.25,1.83 8.23,2.84 8.12,3.01 8.08,3.2 8.08,5.99
Net_32 on BOTTOM (solid shape): 5.26,6.83 5.25,7.53 5.94,7.54 6.93,6.55 7.05,6.39 7.09,6.2 7.09,3.4 7.95,2.54 7.95,1.83 7.24,1.83 6.22,2.84 6.12,3.01 6.1,3.2 6.1,5.99
Net_33 on BOTTOM (solid shape): 23.24,6.83 23.24,7.54 23.95,7.54 24.94,6.55 25.05,6.39 25.1,6.2 25.1,3.4 25.96,2.54 25.96,1.83 25.25,1.83 24.23,2.84 24.12,3.01 24.08,3.2 24.08,5.99
USB_VBUS on L3: 10.31,113.89 12.4,113.89 14.91,111.4 14.91,110.31 14.3,109.7 8.89,109.7 7.9,110.69 7.9,111.51
XDS_VCC on L3: 3.4,108.2 21.11,108.2 23.09,106.2 23.09,92.61 14.61,84.1 7.49,84.1 1.09,90.5 1.09,105.89
N1588336 on TOP: outline of 87 points within 6.86,112.95 15.95,117.55 ; 1 cut-out
N1588336 on TOP: 6.78,112.9 6.78,117.6 8.1,117.6 8.1,115.49 10.01,115.49 10.01,117.6 12.8,117.6 12.8,115.49 14.71,115.49 14.71,117.6 16.05,117.6 16.05,112.9 ; 1 cut-out
N1588336 on BOTTOM, L2: 6.86,112.95 6.86,117.55 8.05,117.55 8.05,115.44 10.06,115.44 10.06,117.55 12.75,117.55 12.75,115.44 14.76,115.44 14.76,117.55 15.95,117.55 15.95,112.95

Small or netless copper shapes (teardrops, artwork), in the pictures only: 16 on TOP

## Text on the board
BOTTOM: 4 | Bottom Layer
Ref Des/Assembly Bottom: Assembly-Bottom | 2
Board Geometry/Soldermask Bottom: Soldermask-Bottom | 6
Package Geometry/Pastemask Bottom: Pastemask-Bottom | 10
Ref Des/Silkscreen Bottom: J1 | 1 | 10 | 21 | 30 | J3 | J4 | 31 | 40 | 11 | 20 | J2 | DIO23 | DIO3 | DIO2 | DIO22 | DIO24 | DIO1 | DIO25 | DIO27 | DIO28 | DIO29 | DIO30 | DIO26 | For evaluation only; not FCC approved for resale. | DIO7 | DIO6 | DIO20 | DIO19 | DIO18 | BPRST | NC | DIO9 | DIO8 | DIO12 | DIO11 | LPRST | DIO13 | DIO14 | DIO15 | DIO10 | DIO21 | DIO4 | DIO5 | TMS | TCK | DIO16 | DIO17 | 8 | Silkscreen-Bottom
User.Comments: BOARD NAME: | CUSTOMER: | PROJECT NO: | LAYER NAME: | BOARD REV: | RELEASE DATE: | SHEET NO: | OF | WCS034 | TEXAS INSTRUMENTS | LAUNCHXL-CC1350-4 | A | 2017-01-23 | 10
TOP: Top Layer | 1
Ref Des/Assembly Top: Assembly-Top | 1 | 2
Board Geometry/Soldermask Top: Soldermask-Top | 5
Package Geometry/Pastemask Top: Pastemask-Top | 9
Ref Des/Silkscreen Top: J1 | 10 | 1 | P2 | 21 | 30 | J3 | P6 | P4 | J4 | P7 | P5 | P10 | 40 | 31 | P1 | 20 | 11 | J2 | DIO23 | DIO22 | DIO24 | DIO3 | DIO2 | DIO13 | BTN-1 | DIO6 | Red: | DIO26 | DIO1 | DIO27 | DIO28 | DIO29 | DIO25 | DIO30 | Green: | DIO7 | CC1350 In | CC-ANTENNA-DK | Mount for: | XDS110 Out | BP | LP | DIO20 | DIO19 | DIO18 | BPRST | VSENSE | DIO14 | BTN-2 | XDS110 | Power | Extern. | Pwr. | LPRST | DIO8 | NC | DIO9 | DIO12 | DIO11 | DIO15 | DIO10 | DIO21 | DIO4 | DIO5 | DIO16 | DIO17 | TMS | TCK | RXD<< | TXD>> | RESET | Reset | TDO | TDI | SWO | Silkscreen-Top | 7 | CC1350 LaunchPad-433MHz | LAUNCHXL-CC1350-4 | Rev:A
L2: Layer-2 | 2
L3: Layer-3 | 3
XSECTION_CHART: *  SURFACE - AIR 0 MIL | L1: TOP CONDUCTOR - COPPER 1.4 MIL | *  DIELECTRIC - FR-4 6.9 MIL | L2: L2 PLANE - COPPER 1.4 MIL | *  DIELECTRIC - FR-4 43.7 MIL | L3: L3 CONDUCTOR - COPPER 1.4 MIL | L4: BOTTOM CONDUCTOR - COPPER 1.4 MIL | DESIGN CROSS SECTION CHART | ___________________________ | TOTAL THICKNESS 63.1 MIL | 1-4
DIMENSION: FAB NOTES: | 1. ALL DIMENSIONS ARE IN INCHES, UNLESS | OTHERWISE NOTED. | 2. THE PWB SHALL BE FABRICATED TO IPC-6012, | CLASS 2 AND WORKMANSHIP SHALL CONFORM TO | IPC-A-600, CLASS 2. CURRENT REVISIONS. | 3. BOARD MATERIAL SHALL BE 180 Tg/340 Td ISOLA | FR-370HR OR EQUIVALENT, RoHS/REACH COMPLIANT AND | LEAD FREE ASSEMBLY CAPABLE. BOARD MATERIAL | SHALL MEET OR EXCEED IPC-4101B. RoHS/REACH | CERTIFICATE OF CONFORMANCE SHALL BE DELIVERED | WITH EACH LOT. | 4. BOARD MATERIAL & CONSTRUCTION TO BE U.L. 94V-0 | APPROVED AND MARKED ON THE FINISHED BOARD.UL | GUIDE NUMBER SHOULD BE MARKED ON THE FINISHED | BOARD. | 5. OVERALL BOARD THICKNESS TO BE .063 +/-.005" | AND APPLIES AFTER ALL LAMINATION AND PLATING | PROCESSES, MEASURED FROM COPPER TO COPPER. | 6. MAX. WARP & TWIST TO BE .0075 PER INCH. | 7. BOARD MUST BE ELECTRICALLY TESTED USING | SUPPLIED IPC-D-356 NETLIST. | 8. 14 MIL TRACES ON LAYER 1 ARE 50 OHMS +/-10%. | THEY ARE REFERENCE TO LAYER 2 GROUND WITH | SOLDERMASK CLEAR AWAY. | PROCESS NOTES: | 1. APPLY LPI SOLDERMASK OVER BARE COPPER (SMOBC), | SOLDERMASK SHALL CONFORM TO IPC-SM-840. CLASS H. | CURRENT REV. COLOR OF MASK TO BE RED. | 2. PLATE ALL EXPOSED AREAS WITH ELECTROLESS NICKEL IMMERSION GOLD. | NICKEL:100 MICRO-INCHES MIN. GOLD:2-8 MICROINCHES MIN. | 3. SOLDERMASK ARTWORK HAS ZERO (0) OVERSIZED PADS. | FABRICATION VENDOR IS ALLOWED TO ADJUST THE COMPONENT SOLDERMASK | PADS TO MEET THEIR TOOLING REQUIREMENTS. | 4. APPLY NON-CONDUCTIVE LPI SILKSCREEN OR EQUIVALENT PER THE ARTWORK. | COLOR: WHITE. | 5. ALL VIAS ARE TENTED. | Fabrication Drawing | 1
DISPLAY_BOTTOM: FIGURE | SIZE | 8.0 | 10.0 | 16.0 | 41.0 | 43.0 | 126.0 | 35.0 | 39.0 | 51.0x24.0 | DRILL CHART: TOP to BOTTOM | ALL UNITS ARE IN MILS | PLATED | NON-PLATED | QTY | 1023 | 28 | 8 | 21 | 75 | 1 | 2 | 6 | 3 | 4
